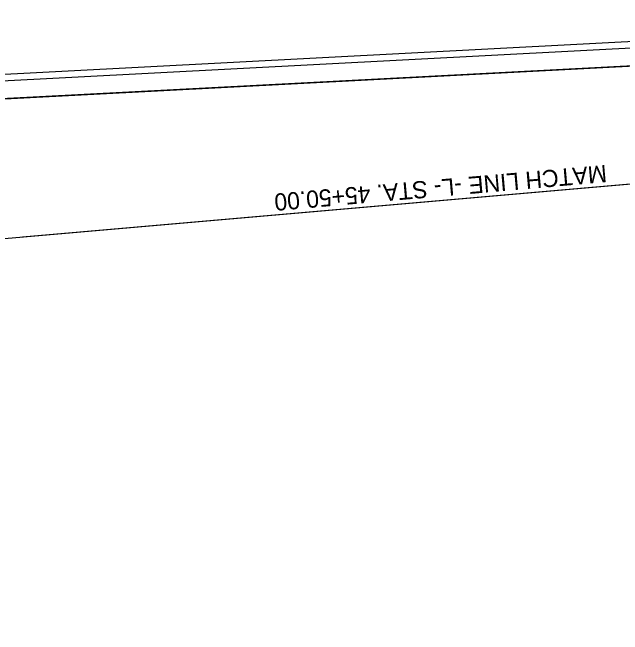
# Model space of a CAD drawing. Extents: x 2368224 to 2369406, y 803271 to 805009.
# Drawn here: x 2368496.5 to 2368923, y 804574.7 to 805009.3 of the extents above; entities that cross this region are included whole.
import ezdxf

# ---------------------------------------------------------------- set-up
doc = ezdxf.new("R2010")
doc.units = 0
for name, color, linetype in [('Old_Level_10', 7, 'Continuous'), ('Old_Level_18', 7, 'Continuous'), ('Old_Level_4', 7, 'Continuous'), ('Old_Level_6', 7, 'Continuous'), ('Old_Level_61', 7, 'Continuous'), ('Old_Level_62', 7, 'Continuous'), ('Old_Level_63', 7, 'Continuous'), ('Plot Shape CELL', 7, 'Continuous')]:
    doc.layers.add(name, color=color, linetype=linetype)

msp = doc.modelspace()

# ---------------------------------------------------------------- linework, layer by layer
at = {"layer": 'Old_Level_10'}
msp.add_lwpolyline([(2368326.05, 803438.23), (2369374.59, 803493.17), (2369296.14, 804991.12), (2368458.77, 804947.26), (2368471.29, 804708.34), (2368260.09, 804697.28)], close=True, dxfattribs=at)
at = {"layer": 'Old_Level_18'}
for points in [[(2369225.56, 803658.81), (2369231.41, 803547.12), (2368322.69, 803502.45), (2368260.09, 804697.28), (2368471.29, 804708.34), (2368463.92, 804849.01), (2369156.05, 804909.28), (2369192.48, 804949.79), (2369298, 804955.52), (2369365.52, 803666.4)], [(2369225.56, 803658.81), (2369231.41, 803547.12), (2368322.69, 803502.45), (2368260.09, 804697.28), (2368471.29, 804708.34), (2368463.92, 804849.01), (2369156.05, 804909.28), (2369183.08, 804698.01), (2369311.04, 804706.52), (2369365.52, 803666.4)]]:
    msp.add_lwpolyline(points, close=True, dxfattribs=at)
at = {"layer": 'Old_Level_4'}
msp.add_lwpolyline([(2369385.12, 803340.02), (2369297.98, 805003.73), (2368244.44, 804948.57), (2368331.57, 803284.85)], close=True, dxfattribs=at)
at = {"layer": 'Old_Level_6'}
msp.add_lwpolyline([(2369405.78, 803328.09), (2369317.73, 805009.28), (2368224.23, 804952.01), (2368312.28, 803270.82)], close=True, dxfattribs=at)
at = {"layer": 'Old_Level_62'}
msp.add_line((2368503.48, 804852.45), (2369025.71, 804897.93), dxfattribs=at)
at = {"layer": 'Old_Level_63'}
msp.add_line((2368761.41, 804874.91), (2368761.41, 804874.91), dxfattribs=at)
at = {"layer": 'Plot Shape CELL'}
for points in [[(2368247.57, 804936.24), (2368326.02, 803438.25), (2369374.59, 803493.17), (2369296.14, 804991.13)], [(2369374.59, 803493.17), (2368326.05, 803438.23), (2368258.03, 804736.44), (2368407.88, 804744.3), (2368397.43, 804944.06), (2369296.14, 804991.13)]]:
    msp.add_lwpolyline(points, close=True, dxfattribs=at)

# ---------------------------------------------------------------- texts
at = {"layer": 'Old_Level_61'}
msp.add_text('MATCH LINE -L- STA. 45+50.00', height=12, rotation=184.9764, dxfattribs=at).set_placement((2368911.43, 804902.8))

doc.saveas('drawing.dxf')
